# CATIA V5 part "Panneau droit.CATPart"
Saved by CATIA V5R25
Part number: Panneau droit
Bounding box of the stored display mesh (mm): x -55 to 55, y -20 to 20, z 0 to 3
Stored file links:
  C:\Users\m000605\Desktop\Projet FAB liseuse\Panneau droit.CATPart
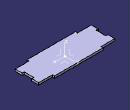
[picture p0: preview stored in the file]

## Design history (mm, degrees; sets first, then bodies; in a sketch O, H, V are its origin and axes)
AxisSystem1: origin (0, 0, 0), X (1, 0, 0), Y (0, 1, 0), Z (0, 0, 1)
Set1
  Sketch1 on XY plane of AxisSystem1, origin (0, 0, 0), H (1, 0, 0), V (0, 1, 0)
    line L1 (-52, 7) -> (-52, -7)
    line L2 (-52, -7) -> (-55, -7)
    line L3 (-35, -17) -> (-35, -20)
    line L4 (-35, -20) -> (35, -20)
    line L5 (35, -20) -> (35, -17)
    point P8 (55, -7)
    line L6 (55, -7) -> (52, -7)
    line L7 (52, -7) -> (52, 7)
    line L8 (52, 7) -> (55, 7)
    point P12 (35, 17)
    line L9 (35, 17) -> (35, 20)
    line L10 (-35, 20) -> (35, 20)
    line L11 (-35, 20) -> (-35, 17)
    line L12 (-55, 7) -> (-52, 7)
    reference intersected line E1 through (0, 0) direction (-1, 0) from ZX plane of AxisSystem1
    reference projected line E2 through (0, 0) direction (1, 0) from edge [XY plane of AxisSystem1 | ZX plane of AxisSystem1]
    line L13 (-35, -17) -> (-55, -17)
    line L14 (-55, -17) -> (-55, -7)
    line L15 (-55, 7) -> (-55, 17)
    line L16 (-55, 17) -> (-35, 17)
    line L17 (35, 17) -> (55, 17)
    line L18 (55, 17) -> (55, 7)
    line L19 (35, -17) -> (55, -17)
    point P20 (55, -17)
    line L20 (55, -17) -> (55, -7)
    reference intersected line E3 through (0, 0) direction (-1, 0) from ZX plane of AxisSystem1
    distance L4 L10 = 40
    distance L18 L15 = 110
    distance L10 L17 = 3
    distance L13 L4 = 3
    distance L7 L18 = 3
    distance L19 L6 = 10
    distance L11 L9 = 70
    vertical: L1 V, L3 V, L5 V, L7 V, L9 V, L11 V, L14 V, L15 V, L18 V, L20 V
    horizontal: L2 H, L4 H, L6 H, L8 H, L10 H, L12 H, L13 H, L16 H, L17 H, L19 H
    coincidence: P8 L2, P12 L5, P20 L18
    symmetry: L1 L7 V, L4 L10 E1, L2 L12 H, L8 L6 E2, L15 L18 V, L20 L14 V, L19 L17 H, L13 L16 E3, L11 L9 V, L3 L5 V
Body1 (main body)
  Pad1: profile Sketch1, direction (0, 0, 1), length 3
